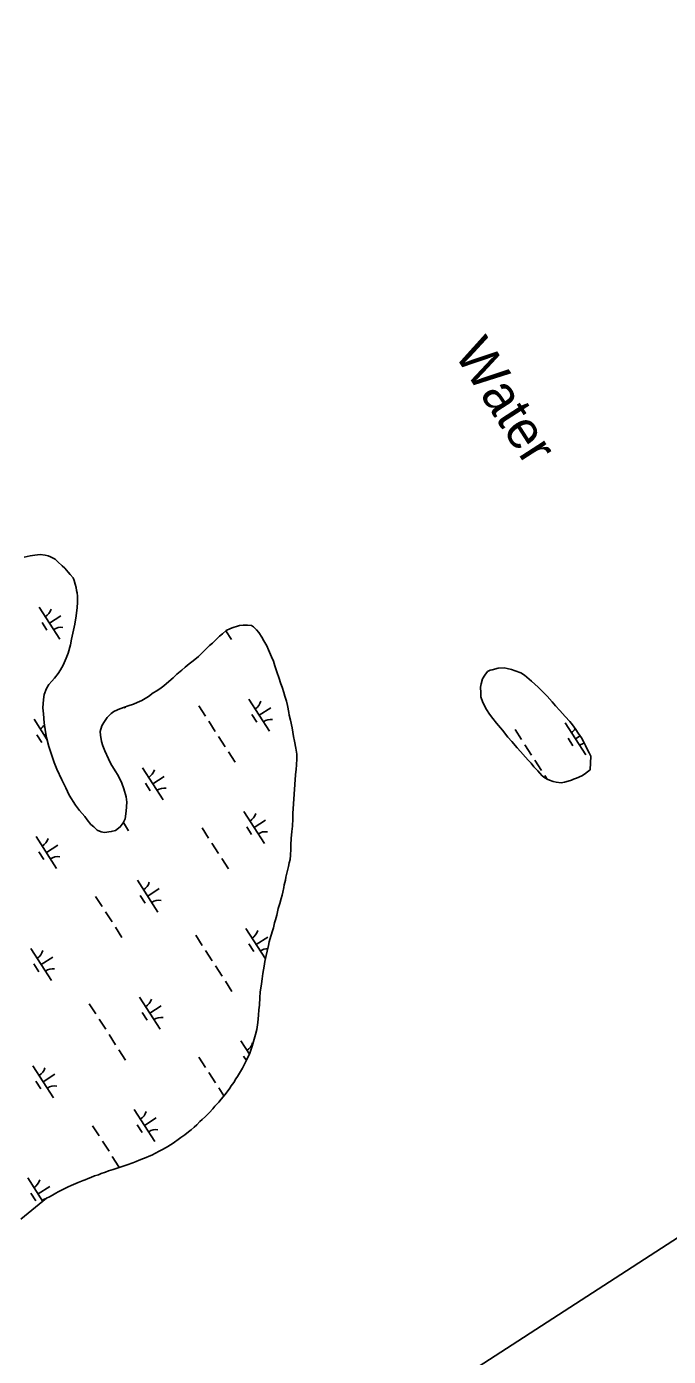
# Model space of a CAD drawing. Extents: x 3937982 to 3958556, y 219448 to 241894.
# Drawn here: x 3954547 to 3955390, y 225653 to 227398 of the extents above; entities that cross this region are included whole.
import ezdxf

# ---------------------------------------------------------------- set-up
doc = ezdxf.new("R2010")
doc.units = 0
for name, color, linetype in [('V-GRID-FRAM', 7, 'Continuous'), ('V-RIVR-IDEN', 7, 'Continuous'), ('V-TOPO-SHOR', 7, 'Continuous'), ('V-WETL-SWMP', 7, 'Continuous')]:
    doc.layers.add(name, color=color, linetype=linetype)

msp = doc.modelspace()

# ---------------------------------------------------------------- linework, layer by layer
at = {"layer": 'V-GRID-FRAM'}
msp.add_lwpolyline([(3948998.173, 239513.74), (3957109.469, 226912.286), (3949780.097, 222173.81), (3941699.799, 234772.334), (3948998.173, 239513.74)], dxfattribs=at)
at = {"layer": 'V-TOPO-SHOR'}
for points in [[(3954677.51, 226387.154), (3954678.538, 226380.248), (3954677.616, 226368.722), (3954676.031, 226358.51), (3954673.758, 226353.231), (3954669.84, 226347.941), (3954663.612, 226343.296), (3954658.027, 226341.618), (3954649.147, 226340.578), (3954644.865, 226341.211), (3954639.585, 226343.484), (3954634.952, 226347.736), (3954631.311, 226351.006), (3954626.338, 226357.23), (3954623.023, 226361.49), (3954616.393, 226369.35), (3954610.757, 226376.23), (3954602.782, 226389.347), (3954598.117, 226399.196), (3954592.788, 226409.696), (3954586.452, 226423.811), (3954582.782, 226432.347), (3954578.425, 226445.487), (3954575.747, 226453.372), (3954573.043, 226465.205), (3954571.681, 226472.766), (3954569.64, 226484.274), (3954568.913, 226496.12), (3954568.206, 226504.342), (3954568.8, 226515.209), (3954569.75, 226521.468), (3954572.664, 226529.713), (3954575.925, 226534.999), (3954579.851, 226538.972), (3954583.447, 226542.943), (3954588.02, 226549.222), (3954591.283, 226554.178), (3954594.867, 226560.124), (3954598.762, 226569.362), (3954601.357, 226575.961), (3954604.257, 226586.84), (3954605.856, 226594.419), (3954608.421, 226606.283), (3954610.022, 226613.861), (3954611.931, 226625.064), (3954613.182, 226635.932), (3954613.803, 226642.519), (3954613.426, 226650.746), (3954613.072, 226655.022), (3954612.394, 226658.311), (3954611.714, 226661.926), (3954610.7, 226666.527), (3954609.354, 226671.457), (3954607.689, 226674.74), (3954604.044, 226678.996), (3954601.392, 226682.272), (3954596.753, 226687.511), (3954593.443, 226690.454), (3954587.816, 226696.017), (3954584.176, 226699.285), (3954578.233, 226702.544), (3954574.934, 226703.84), (3954570.979, 226704.805), (3954564.72, 226705.425), (3954557.487, 226704.397), (3954551.236, 226703.701), (3954543.347, 226702.009)], [(3954894.121, 226324.243), (3954894.401, 226332.472), (3954895.335, 226341.694), (3954895.954, 226348.608), (3954896.554, 226358.488), (3954896.513, 226365.4), (3954900.164, 226416.106), (3954900.779, 226423.682), (3954901.405, 226428.951), (3954902.014, 226437.512), (3954901.649, 226443.435), (3954900.617, 226451.328), (3954898.919, 226460.206), (3954897.565, 226466.45), (3954896.543, 226472.369), (3954895.851, 226477.96), (3954893.49, 226488.149), (3954891.804, 226494.723), (3954891.456, 226498.012), (3954889.427, 226507.216), (3954888.079, 226512.803), (3954886.062, 226519.702), (3954884.718, 226524.302), (3954882.373, 226531.202), (3954880.702, 226535.8), (3954878.019, 226544.012), (3954876.01, 226549.925), (3954872.995, 226559.122), (3954870.982, 226565.364), (3954868.648, 226570.945), (3954864.644, 226580.139), (3954862.309, 226585.392), (3954858.317, 226592.279), (3954855.987, 226596.875), (3954852.001, 226603.105), (3954849.02, 226606.378), (3954845.046, 226610.304), (3954842.402, 226612.264), (3954836.803, 226612.888), (3954831.208, 226612.856), (3954826.604, 226612.171), (3954823.647, 226611.496), (3954818.062, 226609.489), (3954814.447, 226608.479), (3954808.871, 226605.485), (3954803.955, 226601.505), (3954800.355, 226598.194), (3954796.757, 226594.553), (3954790.862, 226589.25), (3954787.262, 226585.939), (3954782.025, 226580.97), (3954776.463, 226575.342), (3954772.535, 226571.699), (3954765.658, 226565.733), (3954760.415, 226561.754), (3954755.172, 226557.445), (3954750.589, 226553.468), (3954744.037, 226548.163), (3954739.456, 226543.529), (3954736.509, 226541.206), (3954733.234, 226538.224), (3954730.612, 226536.236), (3954727.012, 226532.922), (3954723.733, 226530.6), (3954717.835, 226526.287), (3954713.239, 226523.956), (3954706.688, 226518.979), (3954702.424, 226516.321), (3954698.158, 226513.992), (3954691.922, 226510.994), (3954687.326, 226508.991), (3954680.098, 226506.644), (3954675.173, 226504.971), (3954669.258, 226502.962), (3954665.975, 226501.625), (3954661.382, 226499.296), (3954657.775, 226496.64), (3954652.541, 226491.344), (3954648.299, 226485.064), (3954645.364, 226480.44), (3954643.431, 226473.186), (3954643.789, 226468.252), (3954645.155, 226460.032), (3954646.833, 226454.447), (3954649.505, 226447.879), (3954654.177, 226437.045), (3954657.177, 226430.479), (3954663.153, 226421.628), (3954667.141, 226415.398), (3954671.806, 226405.221), (3954674.483, 226397.998), (3954677.51, 226387.154)], [(3955287.193, 226422.658), (3955283.916, 226420.006), (3955279.984, 226417.02), (3955276.376, 226415.025), (3955269.152, 226412.018), (3955265.54, 226410.681), (3955262.587, 226409.018), (3955258.314, 226408.006), (3955253.715, 226406.663), (3955249.113, 226405.647), (3955242.524, 226406.597), (3955238.897, 226407.564), (3955233.951, 226409.18), (3955230.652, 226410.476), (3955227.68, 226412.104), (3955224.373, 226415.047), (3955221.391, 226418.322), (3955218.409, 226421.597), (3955213.113, 226426.832), (3955209.793, 226431.419), (3955205.82, 226435.345), (3955202.177, 226439.603), (3955195.879, 226446.808), (3955191.242, 226451.717), (3955184.283, 226459.905), (3955179.311, 226465.801), (3955172.018, 226474.974), (3955164.063, 226484.143), (3955159.421, 226490.039), (3955155.107, 226495.937), (3955151.122, 226501.84), (3955146.461, 226511.029), (3955143.784, 226518.582), (3955143.424, 226523.845), (3955143.379, 226531.417), (3955144.013, 226535.699), (3955145.619, 226542.292), (3955148.884, 226546.918), (3955152.476, 226551.876), (3955155.757, 226553.541), (3955158.714, 226554.217), (3955166.273, 226556.236), (3955174.17, 226556.611), (3955178.125, 226555.976), (3955183.728, 226554.365), (3955188.674, 226552.747), (3955196.26, 226550.158), (3955201.214, 226547.225), (3955210.147, 226539.377), (3955214.778, 226535.455), (3955219.083, 226531.202), (3955226.036, 226524.331), (3955230.67, 226519.422), (3955237.298, 226511.889), (3955241.607, 226506.978), (3955247.566, 226500.76), (3955250.88, 226496.83), (3955254.526, 226492.9), (3955260.487, 226486.353), (3955264.135, 226481.767), (3955268.452, 226475.539), (3955271.44, 226470.948), (3955276.085, 226464.722), (3955278.416, 226460.128), (3955281.082, 226454.547), (3955283.077, 226450.939), (3955286.073, 226445.032), (3955288.074, 226440.764), (3955287.193, 226422.658)], [(3954595.94, 225872.561), (3954601.519, 225875.555), (3954605.457, 225877.224), (3954608.414, 225878.23), (3954614.653, 225880.9), (3954620.891, 225883.569), (3954623.846, 225884.574), (3954627.786, 225886.244), (3954631.069, 225887.579), (3954635.995, 225889.582), (3954641.252, 225891.259), (3954644.863, 225892.926), (3954650.448, 225894.603), (3954654.388, 225896.273), (3954660.628, 225898.286), (3954670.813, 225901.636), (3954678.696, 225904.315), (3954686.251, 225906.992), (3954690.521, 225908.663), (3954694.459, 225910.332), (3954700.372, 225912.341), (3954703.984, 225913.679), (3954707.595, 225915.675), (3954711.208, 225917.013), (3954716.131, 225919.345), (3954721.05, 225922.008), (3954724.331, 225924.003), (3954730.238, 225926.999), (3954737.78, 225931.652), (3954741.059, 225933.974), (3954745.976, 225937.294), (3954749.581, 225939.948), (3954754.496, 225943.598), (3954759.411, 225947.577), (3954763.016, 225950.231), (3954766.944, 225953.875), (3954770.219, 225956.857), (3954774.47, 225961.159), (3954777.417, 225963.809), (3954781.673, 225967.785), (3954784.29, 225970.433), (3954786.908, 225973.083), (3954791.489, 225977.715), (3954794.102, 225981.023), (3954799.335, 225986.649), (3954802.604, 225990.618), (3954807.179, 225996.24), (3954810.12, 225999.879), (3954813.712, 226004.835), (3954815.67, 226007.811), (3954818.932, 226012.437), (3954821.867, 226017.062), (3954823.823, 226020.365), (3954827.737, 226026.642), (3954830.342, 226031.264), (3954832.945, 226036.546), (3954835.875, 226041.83), (3954840.103, 226050.741), (3954843.011, 226059.973), (3954844.948, 226066.238), (3954847.529, 226075.141), (3954849.136, 226081.733), (3954850.4, 226090.955), (3954851.328, 226100.835), (3954851.946, 226107.751), (3954852.567, 226114.01), (3954853.169, 226123.885), (3954853.785, 226130.801), (3954855.366, 226141.672), (3954856.317, 226148.261), (3954857.261, 226155.508), (3954858.85, 226165.062), (3954859.802, 226170.991), (3954861.4, 226179.23), (3954862.684, 226184.834), (3954864.615, 226192.086), (3954865.576, 226197.028), (3954867.837, 226204.282), (3954868.478, 226207.247), (3954869.446, 226210.217), (3954871.062, 226215.492), (3954872.67, 226222.085), (3954873.634, 226225.71), (3954875.574, 226231.975), (3954876.534, 226236.259), (3954877.497, 226240.543), (3954879.434, 226247.138), (3954881.368, 226254.06), (3954882.66, 226258.349), (3954883.295, 226262.301), (3954884.577, 226268.232), (3954885.214, 226271.857), (3954886.824, 226277.79), (3954887.456, 226282.075), (3954889.064, 226288.665), (3954890.668, 226295.915), (3954891.956, 226300.861), (3954892.916, 226305.146), (3954893.541, 226310.745), (3954893.826, 226318.646), (3954894.121, 226324.243)], [(3954539.233, 225832.731), (3954572.974, 225860.248), (3954576.912, 225862.245), (3954580.846, 225864.574), (3954585.112, 225866.902), (3954588.391, 225868.897), (3954592.657, 225870.896), (3954595.94, 225872.561)]]:
    msp.add_lwpolyline(points, dxfattribs=at)
at = {"layer": 'V-WETL-SWMP'}
for p, q in [((3954563.18, 226636.416), (3954590.242, 226594.373)), ((3954576.711, 226615.394), (3954591.846, 226625.137)), ((3954566.976, 226616.263), (3954573.471, 226606.173)), ((3954808.637, 226605.295), (3954815.95, 226593.934)), ((3954838.875, 226515.427), (3954865.937, 226473.384)), ((3954675.356, 226505.034), (3954676.083, 226503.905)), ((3954773.01, 226506.832), (3954781.67, 226493.378)), ((3954842.671, 226495.275), (3954849.166, 226485.184)), ((3954852.406, 226494.406), (3954867.542, 226504.148)), ((3954556.442, 226489.088), (3954573.718, 226462.247)), ((3954786, 226486.651), (3954794.66, 226473.198)), ((3955254.437, 226484.468), (3955281.5, 226442.425)), ((3954560.238, 226468.935), (3954566.733, 226458.845)), ((3954569.973, 226468.066), (3954572.263, 226469.54)), ((3954798.99, 226466.471), (3954807.65, 226453.017)), ((3955188.572, 226475.873), (3955197.232, 226462.419)), ((3955258.233, 226464.315), (3955264.728, 226454.225)), ((3955267.968, 226463.446), (3955274.094, 226467.389)), ((3954811.98, 226446.29), (3954820.64, 226432.836)), ((3955201.562, 226455.692), (3955210.222, 226442.238)), ((3954699.008, 226425.398), (3954726.07, 226383.354)), ((3955214.552, 226435.511), (3955223.212, 226422.058)), ((3954712.539, 226404.376), (3954727.674, 226414.118)), ((3955227.542, 226415.331), (3955230.671, 226410.47)), ((3954702.804, 226405.245), (3954709.299, 226395.155)), ((3954832.137, 226368.099), (3954859.199, 226326.056)), ((3954845.668, 226347.077), (3954860.804, 226356.82)), ((3954673.88, 226353.514), (3954680.772, 226342.807)), ((3954777.271, 226346.702), (3954785.931, 226333.248)), ((3954835.933, 226347.947), (3954842.428, 226337.856)), ((3954559.14, 226335.368), (3954586.203, 226293.325)), ((3954572.671, 226314.347), (3954587.807, 226324.089)), ((3954790.261, 226326.521), (3954798.921, 226313.067)), ((3954562.936, 226315.216), (3954569.431, 226305.125)), ((3954803.251, 226306.34), (3954811.911, 226292.887)), ((3954692.27, 226278.07), (3954719.332, 226236.026)), ((3954637.404, 226256.672), (3954646.063, 226243.219)), ((3954696.066, 226257.917), (3954702.561, 226247.827)), ((3954705.801, 226257.048), (3954720.936, 226266.79)), ((3954650.393, 226236.492), (3954659.053, 226223.038)), ((3954663.383, 226216.311), (3954672.043, 226202.857)), ((3954768.97, 226205.784), (3954777.63, 226192.331)), ((3954834.835, 226214.379), (3954860.488, 226174.526)), ((3954848.367, 226193.358), (3954863.502, 226203.1)), ((3954552.402, 226188.04), (3954579.465, 226145.997)), ((3954781.96, 226185.604), (3954790.62, 226172.15)), ((3954838.631, 226194.227), (3954845.126, 226184.137)), ((3954556.198, 226167.888), (3954562.693, 226157.797)), ((3954565.933, 226167.018), (3954581.069, 226176.761)), ((3954794.95, 226165.423), (3954803.61, 226151.969)), ((3954807.94, 226145.242), (3954816.6, 226131.788)), ((3954629.103, 226115.755), (3954637.763, 226102.301)), ((3954694.968, 226124.35), (3954722.03, 226082.307)), ((3954708.499, 226103.328), (3954723.635, 226113.071)), ((3954642.093, 226095.574), (3954650.753, 226082.12)), ((3954698.764, 226104.197), (3954705.259, 226094.107)), ((3954655.083, 226075.393), (3954663.743, 226061.94)), ((3954828.097, 226067.051), (3954839.463, 226049.394)), ((3954668.073, 226055.213), (3954676.733, 226041.759)), ((3954773.231, 226045.654), (3954781.891, 226032.2)), ((3954831.893, 226046.899), (3954835.543, 226041.229)), ((3954555.101, 226034.32), (3954582.163, 225992.277)), ((3954786.221, 226025.473), (3954794.881, 226012.02)), ((3954558.897, 226014.168), (3954565.392, 226004.078)), ((3954568.632, 226013.299), (3954583.768, 226023.041)), ((3954799.211, 226005.293), (3954805.984, 225994.771)), ((3954688.23, 225977.022), (3954715.292, 225934.979)), ((3954633.364, 225955.625), (3954642.024, 225942.171)), ((3954692.026, 225956.869), (3954698.521, 225946.779)), ((3954701.761, 225956), (3954716.897, 225965.743)), ((3954646.354, 225935.444), (3954655.014, 225921.99)), ((3954659.344, 225915.263), (3954668.004, 225901.809)), ((3954548.363, 225886.992), (3954568.123, 225856.293)), ((3954552.159, 225866.84), (3954558.654, 225856.75)), ((3954561.894, 225865.971), (3954577.03, 225875.713))]:
    msp.add_line(p, q, dxfattribs=at)
for points in [[(3954543.348, 226702.009), (3954551.237, 226703.701), (3954557.486, 226704.396), (3954564.721, 226705.426), (3954570.979, 226704.804), (3954574.934, 226703.84), (3954578.233, 226702.543), (3954584.177, 226699.286), (3954587.816, 226696.016), (3954593.444, 226690.454), (3954596.753, 226687.511), (3954601.392, 226682.272), (3954604.044, 226678.996), (3954607.689, 226674.739), (3954609.354, 226671.457), (3954610.7, 226666.528), (3954611.714, 226661.926), (3954612.394, 226658.31), (3954613.071, 226655.022), (3954613.426, 226650.746), (3954613.803, 226642.519), (3954613.183, 226635.933), (3954611.931, 226625.064), (3954610.022, 226613.862), (3954608.42, 226606.283), (3954605.857, 226594.419), (3954604.256, 226586.839), (3954601.357, 226575.961), (3954598.763, 226569.363), (3954594.867, 226560.124), (3954591.282, 226554.178), (3954588.02, 226549.222), (3954583.448, 226542.942), (3954579.851, 226538.971), (3954575.925, 226534.998), (3954572.665, 226529.713), (3954569.751, 226521.467), (3954568.8, 226515.208), (3954568.205, 226504.343), (3954568.912, 226496.119), (3954569.64, 226484.274), (3954571.682, 226472.766), (3954573.043, 226465.204), (3954575.746, 226453.371), (3954578.425, 226445.487), (3954582.781, 226432.347), (3954586.452, 226423.811), (3954592.788, 226409.696), (3954598.116, 226399.195), (3954602.782, 226389.348), (3954610.758, 226376.229), (3954616.394, 226369.35), (3954623.022, 226361.49), (3954626.339, 226357.231), (3954631.312, 226351.006), (3954634.952, 226347.736), (3954639.585, 226343.484), (3954644.864, 226341.211), (3954649.147, 226340.578), (3954658.028, 226341.618), (3954663.613, 226343.296), (3954669.839, 226347.941), (3954673.758, 226353.23), (3954676.031, 226358.51), (3954677.617, 226368.722), (3954678.537, 226380.247), (3954677.509, 226387.153), (3954674.483, 226397.997)], [(3954674.483, 226397.997), (3954671.807, 226405.222), (3954667.14, 226415.398), (3954663.153, 226421.628), (3954657.177, 226430.48), (3954654.176, 226437.045), (3954649.505, 226447.879), (3954646.833, 226454.446), (3954645.155, 226460.032), (3954643.79, 226468.252), (3954643.432, 226473.187), (3954645.364, 226480.44), (3954648.299, 226485.065), (3954652.541, 226491.343), (3954657.776, 226496.64), (3954661.381, 226499.295), (3954665.975, 226501.625), (3954669.259, 226502.961), (3954675.172, 226504.971), (3954680.099, 226506.645), (3954687.326, 226508.992), (3954691.922, 226510.994), (3954698.158, 226513.992), (3954702.423, 226516.321), (3954706.687, 226518.98), (3954713.24, 226523.955), (3954717.834, 226526.286), (3954723.734, 226530.599), (3954727.011, 226532.923), (3954730.612, 226536.235), (3954733.234, 226538.225), (3954736.508, 226541.207), (3954739.456, 226543.528), (3954744.037, 226548.163), (3954750.589, 226553.468), (3954755.173, 226557.444), (3954760.414, 226561.754), (3954765.657, 226565.734), (3954772.534, 226571.699), (3954776.462, 226575.342), (3954782.025, 226580.97), (3954787.262, 226585.938), (3954790.863, 226589.251), (3954796.756, 226594.552), (3954800.355, 226598.193), (3954803.956, 226601.506), (3954808.87, 226605.484), (3954814.448, 226608.479), (3954818.062, 226609.488), (3954823.646, 226611.495), (3954826.604, 226612.171), (3954831.208, 226612.856), (3954836.803, 226612.889), (3954842.402, 226612.264), (3954845.047, 226610.304), (3954849.02, 226606.378), (3954852.001, 226603.104), (3954855.987, 226596.874), (3954858.318, 226592.28), (3954862.308, 226585.391), (3954864.643, 226580.139), (3954868.647, 226570.946), (3954870.983, 226565.365), (3954872.995, 226559.123), (3954876.011, 226549.925), (3954878.02, 226544.012), (3954880.702, 226535.799), (3954882.374, 226531.201), (3954884.719, 226524.303), (3954886.062, 226519.703), (3954888.078, 226512.803), (3954889.427, 226507.216), (3954891.456, 226498.012), (3954891.804, 226494.722), (3954893.489, 226488.149), (3954895.852, 226477.96), (3954896.543, 226472.369), (3954897.566, 226466.45), (3954898.919, 226460.205), (3954900.617, 226451.328), (3954901.65, 226443.435), (3954902.014, 226437.512), (3954901.406, 226428.951), (3954900.779, 226423.681), (3954900.165, 226416.107), (3954896.513, 226365.399), (3954896.554, 226358.487), (3954895.953, 226348.609), (3954895.336, 226341.694), (3954894.402, 226332.473), (3954894.121, 226324.243), (3954893.825, 226318.645), (3954893.542, 226310.744), (3954892.917, 226305.145), (3954891.955, 226300.861), (3954890.667, 226295.916), (3954889.064, 226288.666), (3954887.457, 226282.074), (3954886.824, 226277.791), (3954885.213, 226271.857), (3954884.576, 226268.233)], [(3954884.576, 226268.233), (3954883.294, 226262.301), (3954882.659, 226258.348), (3954881.368, 226254.061), (3954879.434, 226247.138), (3954877.497, 226240.544), (3954876.535, 226236.26), (3954875.573, 226231.975), (3954873.635, 226225.71), (3954872.669, 226222.084), (3954871.062, 226215.492), (3954869.447, 226210.216), (3954868.477, 226207.248), (3954867.836, 226204.282), (3954865.575, 226197.028), (3954864.616, 226192.085), (3954862.684, 226184.833), (3954861.4, 226179.23), (3954859.803, 226170.992), (3954858.85, 226165.062), (3954857.261, 226155.508), (3954856.316, 226148.261), (3954855.367, 226141.673), (3954853.785, 226130.802), (3954853.168, 226123.886), (3954852.567, 226114.009), (3954851.946, 226107.751), (3954851.328, 226100.836), (3954850.399, 226090.956), (3954849.136, 226081.733), (3954847.529, 226075.141), (3954844.948, 226066.239), (3954843.01, 226059.974), (3954840.102, 226050.741), (3954835.876, 226041.83), (3954832.944, 226036.546), (3954830.342, 226031.265), (3954827.736, 226026.642), (3954823.823, 226020.365), (3954821.868, 226017.062), (3954818.933, 226012.437), (3954815.669, 226007.81), (3954813.711, 226004.836), (3954810.12, 225999.878), (3954807.179, 225996.24), (3954802.604, 225990.618), (3954799.336, 225986.649), (3954794.103, 225981.023), (3954791.489, 225977.716), (3954786.908, 225973.082), (3954784.291, 225970.433), (3954781.673, 225967.785), (3954777.418, 225963.81), (3954774.471, 225961.16), (3954770.218, 225956.856), (3954766.944, 225953.874), (3954763.015, 225950.231), (3954759.411, 225947.577), (3954754.497, 225943.598), (3954749.581, 225939.949), (3954745.976, 225937.295), (3954741.059, 225933.974), (3954737.781, 225931.651), (3954730.238, 225926.999), (3954724.331, 225924.002), (3954721.051, 225922.008), (3954716.13, 225919.346), (3954711.207, 225917.013), (3954707.594, 225915.675), (3954703.985, 225913.679), (3954700.372, 225912.342), (3954694.46, 225910.332), (3954690.52, 225908.663), (3954686.251, 225906.992), (3954678.696, 225904.315), (3954670.813, 225901.636), (3954660.629, 225898.285), (3954654.387, 225896.273), (3954650.448, 225894.604), (3954644.862, 225892.926), (3954641.251, 225891.259), (3954635.995, 225889.582), (3954631.07, 225887.579), (3954627.786, 225886.243), (3954623.846, 225884.574), (3954620.89, 225883.569), (3954614.652, 225880.9), (3954608.414, 225878.23), (3954605.458, 225877.225), (3954601.518, 225875.556), (3954595.94, 225872.561), (3954592.658, 225870.896), (3954588.391, 225868.897), (3954585.112, 225866.902), (3954580.847, 225864.573), (3954576.911, 225862.246), (3954572.973, 225860.248), (3954539.233, 225832.732)]]:
    msp.add_lwpolyline(points, dxfattribs=at)
msp.add_lwpolyline([(3955287.193, 226422.657), (3955283.917, 226420.005), (3955279.985, 226417.02), (3955276.376, 226415.024), (3955269.152, 226412.019), (3955265.54, 226410.681), (3955262.587, 226409.018), (3955258.314, 226408.006), (3955253.714, 226406.662), (3955249.112, 226405.648), (3955242.524, 226406.597), (3955238.898, 226407.563), (3955233.951, 226409.18), (3955230.652, 226410.477), (3955227.681, 226412.105), (3955224.372, 226415.048), (3955221.391, 226418.322), (3955218.409, 226421.596), (3955213.112, 226426.831), (3955209.794, 226431.419), (3955205.821, 226435.345), (3955202.176, 226439.603), (3955195.88, 226446.807), (3955191.243, 226451.717), (3955184.283, 226459.904), (3955179.311, 226465.8), (3955172.017, 226474.973), (3955164.063, 226484.142), (3955159.421, 226490.039), (3955155.107, 226495.938), (3955151.123, 226501.839), (3955146.461, 226511.028), (3955143.784, 226518.582), (3955143.424, 226523.846), (3955143.379, 226531.416), (3955144.013, 226535.699), (3955145.62, 226542.291), (3955148.884, 226546.918), (3955152.475, 226551.876), (3955155.757, 226553.541), (3955158.715, 226554.217), (3955166.273, 226556.236), (3955174.171, 226556.612), (3955178.124, 226555.976), (3955183.729, 226554.364), (3955188.675, 226552.747), (3955196.261, 226550.158), (3955201.215, 226547.225), (3955210.148, 226539.378), (3955214.779, 226535.456), (3955219.082, 226531.202), (3955226.035, 226524.331), (3955230.671, 226519.421), (3955237.298, 226511.89), (3955241.606, 226506.978), (3955247.567, 226500.76), (3955250.881, 226496.83), (3955254.525, 226492.901), (3955260.488, 226486.353), (3955264.135, 226481.767), (3955268.451, 226475.539), (3955271.44, 226470.948), (3955276.084, 226464.722), (3955278.415, 226460.128), (3955281.081, 226454.548), (3955283.077, 226450.939), (3955286.074, 226445.032), (3955288.074, 226440.765)], close=True, dxfattribs=at)
for centre, start, end in [((3954561.961, 226638.749), 301.99668, 343.540338), ((3954591.861, 226592.297), 81.996677, 123.540335), ((3954837.656, 226517.76), 301.99668, 343.540338), ((3954555.223, 226491.421), 301.99668, 327.34104), ((3954867.556, 226471.308), 81.996677, 123.540335), ((3955253.218, 226486.801), 301.99668, 324.993133), ((3955283.118, 226440.349), 101.471083, 123.540335), ((3954697.788, 226427.73), 301.99668, 343.540338), ((3954727.688, 226381.279), 81.996677, 123.540335), ((3954830.918, 226370.432), 301.99668, 343.540338), ((3954860.818, 226323.98), 81.996677, 123.540335), ((3954557.921, 226337.701), 301.99668, 343.540338), ((3954587.821, 226291.249), 81.996677, 123.540335), ((3954691.05, 226280.402), 301.99668, 343.540338), ((3954720.95, 226233.951), 81.996677, 123.540335), ((3954833.616, 226216.712), 301.99668, 343.540338), ((3954551.183, 226190.373), 301.99668, 343.540338), ((3954863.516, 226170.26), 90.063593, 123.540335), ((3954581.083, 226143.921), 81.996677, 123.540335), ((3954693.749, 226126.683), 301.99668, 343.540338), ((3954723.649, 226080.231), 81.996677, 123.540335), ((3954826.878, 226069.384), 301.99668, 343.540338), ((3954553.882, 226036.653), 301.99668, 343.540338), ((3954583.782, 225990.201), 81.996677, 123.540335), ((3954687.011, 225979.355), 301.99668, 343.540338), ((3954716.911, 225932.903), 81.996677, 123.540335), ((3954547.144, 225889.325), 301.99668, 343.540338), ((3954577.044, 225842.873), 104.706956, 123.540335)]:
    msp.add_arc(centre, 17.623, start, end, dxfattribs=at)

# ---------------------------------------------------------------- texts
at = {"layer": 'V-RIVR-IDEN'}
msp.add_text('Water', height=49.9999, rotation=302.768556, dxfattribs=at).set_placement((3955107.679, 226969.159))

doc.saveas('drawing.dxf')
